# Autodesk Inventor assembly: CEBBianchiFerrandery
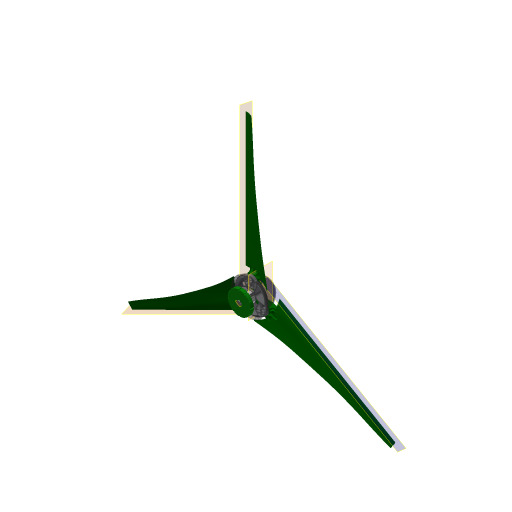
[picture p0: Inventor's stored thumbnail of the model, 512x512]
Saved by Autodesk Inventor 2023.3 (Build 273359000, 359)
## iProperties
Created: 2018-01
Part Number: CEBBianchiFerrandery
Document SubType Name: Assembly
Designer: formation
Author: formation
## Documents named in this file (7)
- C:\Travail\BTS TechCom\2-TechnoIndus\21-Meca\214-Systémes Industriels-SI\2141-Pièces Ecrites\21411-Cycle1\214112-TP02Eolienne\2141122-DossierTechniqueEolienne\21411223-Maquette numerique\214112233-CEC-Eolienne\CEC-Eoliene.iam
- C:\Travail\BTS TechCom\2-TechnoIndus\21-Meca\214-Systémes Industriels-SI\2141-Pièces Ecrites\21411-Cycle1\214112-TP02Eolienne\2141122-DossierTechniqueEolienne\21411223-Maquette numerique\214112233-CEC-Eolienne\07-Arbre rotor.ipt
- C:\Travail\BTS TechCom\2-TechnoIndus\21-Meca\214-Systémes Industriels-SI\2141-Pièces Ecrites\21411-Cycle1\214112-TP02Eolienne\2141122-DossierTechniqueEolienne\21411223-Maquette numerique\214112233-CEC-Eolienne\08-Rotor.ipt
- C:\Travail\BTS TechCom\2-TechnoIndus\21-Meca\214-Systémes Industriels-SI\2141-Pièces Ecrites\21411-Cycle1\214112-TP02Eolienne\2141122-DossierTechniqueEolienne\21411223-Maquette numerique\214112233-CEC-Eolienne\10-Entretoise.ipt
- C:\Travail\BTS TechCom\2-TechnoIndus\21-Meca\214-Systémes Industriels-SI\2141-Pièces Ecrites\21411-Cycle1\214112-TP02Eolienne\2141122-DossierTechniqueEolienne\21411223-Maquette numerique\214112233-CEC-Eolienne\09-BS 290 SKF - SKF 6203-RS1.ipt
- C:\Travail\BTS TechCom\2-TechnoIndus\21-Meca\214-Systémes Industriels-SI\2141-Pièces Ecrites\21411-Cycle1\214112-TP02Eolienne\2141122-DossierTechniqueEolienne\21411223-Maquette numerique\214112233-CEC-Eolienne\Helice\Hélice.iam
- C:\Users\Thier\OneDrive\Documents\Inventor\Content Center Files\R2023\fr-FR\ISO 4032(3)\ISO 4032 - M18NF EN.ipt
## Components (7 placed, 6 different names)
1. 07-Arbre rotor:1 — Angle:1, Logement:5
2. 08-Rotor:1 — Logement:1, Angle:1, Logement:5
3. 10-Entretoise:1 — Logement:8, Logement:9
4. BS 290 SKF- with RS1 seal SKF 6203-RS1:1 — Logement:1, Logement:8
5. BS 290 SKF- with RS1 seal SKF 6203-RS1:2 — Logement:6, Logement:9
6. Hélice:1 [sub-assembly] — Logement:6, Logement:7
7. NF EN 24032 M18:1 — Logement:7
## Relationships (7: Insert 6, Angle 1)
- Logement:1 [Insert]: 08-Rotor:1 ↔ BS 290 SKF- with RS1 seal SKF 6203-RS1:1
- Angle:1: 07-Arbre rotor:1 ↔ 08-Rotor:1
- Logement:5 [Insert]: 07-Arbre rotor:1 ↔ 08-Rotor:1
- Logement:6 [Insert]: BS 290 SKF- with RS1 seal SKF 6203-RS1:2 ↔ Hélice:1
- Logement:7 [Insert]: Hélice:1 ↔ NF EN 24032 M18:1
- Logement:8 [Insert]: 10-Entretoise:1 ↔ BS 290 SKF- with RS1 seal SKF 6203-RS1:1
- Logement:9 [Insert]: 10-Entretoise:1 ↔ BS 290 SKF- with RS1 seal SKF 6203-RS1:2
